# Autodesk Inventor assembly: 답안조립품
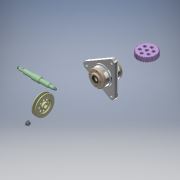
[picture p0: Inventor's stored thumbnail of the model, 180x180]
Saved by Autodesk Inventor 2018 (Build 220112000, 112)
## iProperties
Created: 2023-04
Part Number: 답안조립품
Material: 일반
Document SubType Name: Assembly
Designer: home
Author: home
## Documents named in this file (11)
- C:\Users\home\Desktop\730407V1003\답안조립품.iam
- C:\Users\home\Desktop\730407V1003\6각 플랜지 너트 M10.ipt
- C:\Users\home\Desktop\730407V1003\v-벨트풀리.ipt
- C:\Users\home\Desktop\730407V1003\묻힘키 5x5x16.ipt
- C:\Users\home\Desktop\730407V1003\베어링 6204.ipt
- C:\Users\home\Desktop\730407V1003\본체.ipt
- C:\Users\home\Desktop\730407V1003\볼트 M4 x 12.ipt
- C:\Users\home\Desktop\730407V1003\스퍼기어.ipt
- C:\Users\home\Desktop\730407V1003\오일 실 20 32 8.ipt
- C:\Users\home\Desktop\730407V1003\축.ipt
- C:\Users\home\Desktop\730407V1003\커버.ipt
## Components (2 placed, 2 different names)
1. 6각 플랜지 너트 M10:1
2. v-벨트풀리:1
